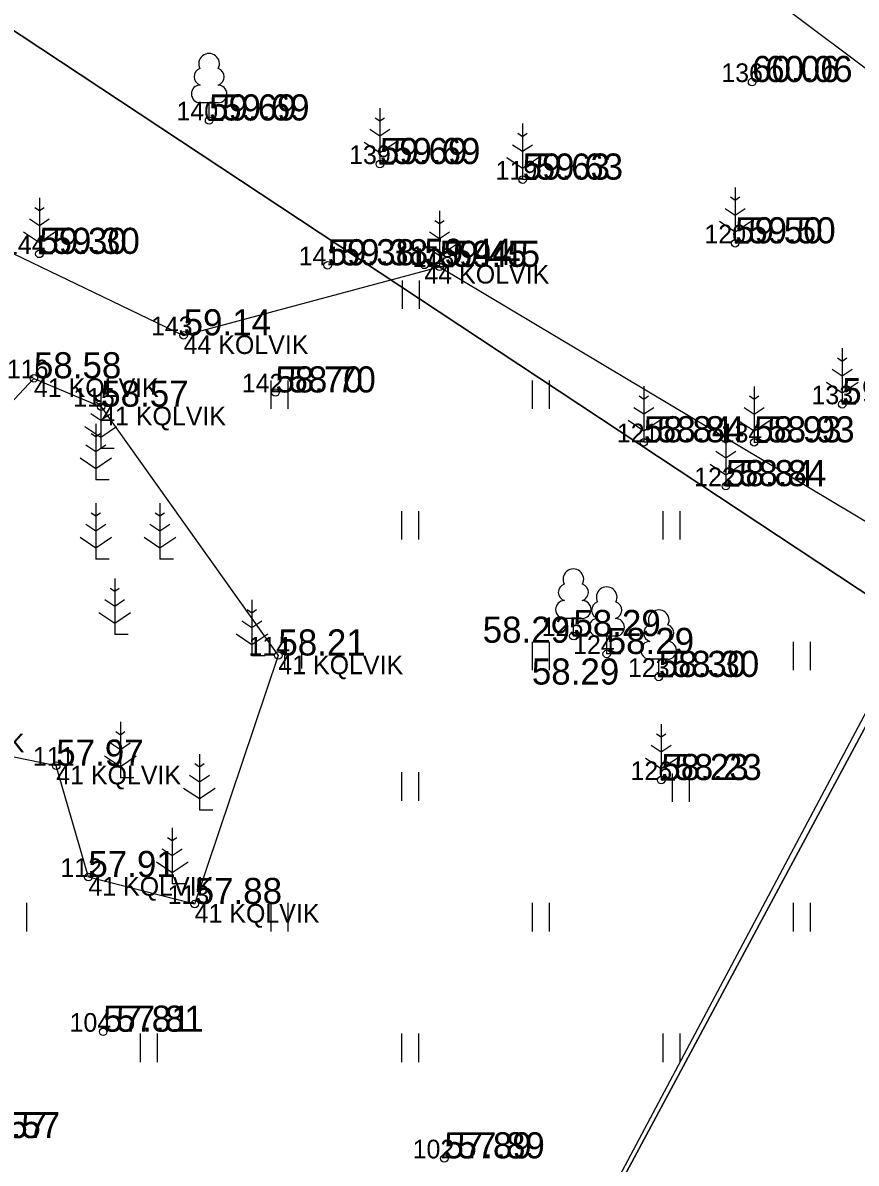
# Model space of a CAD drawing. Extents: x 640891 to 641083, y 6456526 to 6456669.
# Drawn here: x 640961.9 to 640984.23, y 6456618.41 to 6456648.96 of the extents above; entities that cross this region are included whole.
import ezdxf

# ---------------------------------------------------------------- set-up
doc = ezdxf.new("R2010")
doc.units = 0
for name, color, linetype in [('100koma2', 7, 'Continuous'), ('HALJASTUS', 7, 'Continuous'), ('KORGUS', 7, 'Continuous'), ('MOOTKORG', 7, 'Continuous'), ('MOOTMPUNKT', 7, 'Continuous'), ('MOOTNR', 7, 'Continuous'), ('MOOTPIIR', 7, 'Continuous'), ('PIIR', 7, 'Continuous'), ('PUU', 7, 'Continuous')]:
    doc.layers.add(name, color=color, linetype=linetype)

msp = doc.modelspace()

# ---------------------------------------------------------------- linework, layer by layer
at = {"layer": 'HALJASTUS'}
for p, q in [((640972.067, 6456642.056), (640972.067, 6456641.294)), ((640972.522, 6456642.056), (640972.522, 6456641.294)), ((640968.545, 6456639.381), (640968.545, 6456638.619)), ((640969, 6456639.381), (640969, 6456638.619)), ((640975.545, 6456639.381), (640975.545, 6456638.619)), ((640976, 6456639.381), (640976, 6456638.619)), ((640972.045, 6456635.881), (640972.045, 6456635.119)), ((640972.5, 6456635.881), (640972.5, 6456635.119)), ((640979.045, 6456635.881), (640979.045, 6456635.119)), ((640979.5, 6456635.881), (640979.5, 6456635.119)), ((640968.91, 6456632.425), (640968.91, 6456631.664)), ((640969.365, 6456632.425), (640969.365, 6456631.664)), ((640975.545, 6456632.381), (640975.545, 6456631.619)), ((640976, 6456632.381), (640976, 6456631.619)), ((640982.545, 6456632.381), (640982.545, 6456631.619)), ((640983, 6456632.381), (640983, 6456631.619)), ((640972.045, 6456628.881), (640972.045, 6456628.119)), ((640972.5, 6456628.881), (640972.5, 6456628.119)), ((640979.299, 6456628.852), (640979.299, 6456628.091)), ((640979.754, 6456628.852), (640979.754, 6456628.091)), ((640962, 6456625.381), (640962, 6456624.619)), ((640968.545, 6456625.381), (640968.545, 6456624.619)), ((640969, 6456625.381), (640969, 6456624.619)), ((640975.545, 6456625.381), (640975.545, 6456624.619)), ((640976, 6456625.381), (640976, 6456624.619)), ((640982.545, 6456625.381), (640982.545, 6456624.619)), ((640983, 6456625.381), (640983, 6456624.619)), ((640965.045, 6456621.881), (640965.045, 6456621.119)), ((640965.5, 6456621.881), (640965.5, 6456621.119)), ((640972.045, 6456621.881), (640972.045, 6456621.119)), ((640972.5, 6456621.881), (640972.5, 6456621.119)), ((640979.045, 6456621.881), (640979.045, 6456621.119)), ((640979.5, 6456621.881), (640979.5, 6456621.119))]:
    msp.add_line(p, q, dxfattribs=at)
for points in [[(640946.505, 6456648.924), (640957.822, 6456644.615), (640966.207, 6456640.588), (640973.066, 6456642.422), (640986.679, 6456634.293)], [(640940.859, 6456588.363), (640936.098, 6456589.959), (640937.267, 6456594.734), (640939.119, 6456600.434), (640944.153, 6456613.282), (640950.33, 6456623.315), (640954.177, 6456630.888), (640962.196, 6456639.436), (640963.998, 6456638.677), (640968.745, 6456632.01), (640966.503, 6456625.352), (640963.655, 6456626.075), (640962.794, 6456629.058), (640958.598, 6456629.914), (640954.818, 6456622.648), (640946.439, 6456612.875), (640948.12, 6456609.151), (640945.862, 6456604.895), (640949.763, 6456601.734), (640945.05, 6456592.964), (640940.483, 6456588.68)], [(640962.925, 6456576.62), (640957.383, 6456579.521), (640966.138, 6456596.056), (640972.417, 6456607.592), (640977.059, 6456616.501), (640985.041, 6456631.518)]]:
    msp.add_lwpolyline(points, dxfattribs=at)
at = {"layer": 'KORGUS'}
for centre in [(640981.44, 6456647.374), (640966.89, 6456646.344), (640971.467, 6456645.177), (640975.291, 6456644.76), (640980.987, 6456643.053), (640962.342, 6456642.77), (640970.066, 6456642.464), (640973.066, 6456642.422), (640968.666, 6456639.057), (640983.856, 6456638.741), (640978.539, 6456637.722), (640981.496, 6456637.721), (640980.738, 6456636.547), (640976.651, 6456632.531), (640977.544, 6456632.051), (640978.939, 6456631.436), (640979.007, 6456628.673), (640964.051, 6456621.93), (640973.194, 6456618.537)]:
    msp.add_circle(centre, 0.1, dxfattribs=at)
at = {"layer": 'MOOTMPUNKT'}
for centre in [(640981.44, 6456647.374), (640966.89, 6456646.344), (640971.467, 6456645.177), (640975.291, 6456644.76), (640980.987, 6456643.053), (640962.342, 6456642.77), (640970.066, 6456642.464), (640972.66, 6456642.475), (640973.066, 6456642.422), (640966.207, 6456640.588), (640962.196, 6456639.436), (640968.666, 6456639.057), (640963.998, 6456638.677), (640983.856, 6456638.741), (640978.539, 6456637.722), (640981.496, 6456637.721), (640980.738, 6456636.547), (640976.651, 6456632.531), (640968.745, 6456632.01), (640977.544, 6456632.051), (640978.939, 6456631.436), (640962.794, 6456629.058), (640979.007, 6456628.673), (640963.655, 6456626.075), (640966.503, 6456625.352), (640964.051, 6456621.93), (640973.194, 6456618.537)]:
    msp.add_circle(centre, 0.1, dxfattribs=at)
at = {"layer": 'MOOTPIIR'}
msp.add_lwpolyline([(640924.706, 6456598.502), (640938.233, 6456631.58), (640948.873, 6456653.866), (640953.873, 6456657.504), (640964.983, 6456662.356), (640986.497, 6456646.235), (640995.587, 6456643.81), (640989.565, 6456627.418), (640994.744, 6456619.938), (640993.953, 6456602.696)], dxfattribs=at)
at = {"layer": 'PIIR'}
msp.add_lwpolyline([(641039.59, 6456660.086), (641000.58, 6456623), (640985.89, 6456632.73), (640960.76, 6456649.34), (640935.64, 6456665.95), (640931.367, 6456668.776)], dxfattribs=at)
for points in [[(640957.22, 6456579.32), (640930.79, 6456593.51), (640960.76, 6456649.34), (640985.89, 6456632.73)], [(640983.63, 6456565.13), (640957.22, 6456579.32), (640985.89, 6456632.73), (641000.58, 6456623), (641011.01, 6456616.1)]]:
    msp.add_lwpolyline(points, close=True, dxfattribs=at)
at = {"layer": 'PUU'}
for p, q in [((640967.13, 6456646.819), (640966.65, 6456646.819)), ((640966.89, 6456646.344), (640966.89, 6456646.819)), ((640971.467, 6456646.677), (640971.467, 6456645.177)), ((640967.27, 6456646.344), (640966.89, 6456646.344)), ((640971.467, 6456646.327), (640971.342, 6456646.41)), ((640971.591, 6456646.41), (640971.467, 6456646.327)), ((640975.291, 6456646.26), (640975.291, 6456644.76)), ((640971.467, 6456645.927), (640971.2, 6456646.105)), ((640971.733, 6456646.105), (640971.467, 6456645.927)), ((640975.291, 6456645.91), (640975.167, 6456645.993)), ((640975.415, 6456645.993), (640975.291, 6456645.91)), ((640971.042, 6456645.766), (640971.467, 6456645.484)), ((640971.467, 6456645.484), (640971.891, 6456645.766)), ((640975.291, 6456645.51), (640975.024, 6456645.687)), ((640975.558, 6456645.687), (640975.291, 6456645.51)), ((640974.867, 6456645.349), (640975.291, 6456645.066)), ((640975.291, 6456645.066), (640975.715, 6456645.349)), ((640971.827, 6456645.177), (640971.467, 6456645.177)), ((640975.651, 6456644.76), (640975.291, 6456644.76)), ((640980.987, 6456644.203), (640980.863, 6456644.286)), ((640980.987, 6456644.553), (640980.987, 6456643.053)), ((640981.112, 6456644.286), (640980.987, 6456644.203)), ((640962.342, 6456643.92), (640962.217, 6456644.003)), ((640962.342, 6456644.27), (640962.342, 6456642.77)), ((640962.466, 6456644.003), (640962.342, 6456643.92)), ((640980.987, 6456643.803), (640980.721, 6456643.981)), ((640981.254, 6456643.981), (640980.987, 6456643.803)), ((640962.342, 6456643.52), (640962.075, 6456643.698)), ((640962.608, 6456643.698), (640962.342, 6456643.52)), ((640973.066, 6456643.922), (640973.066, 6456642.422)), ((640961.917, 6456643.36), (640962.342, 6456643.077)), ((640962.342, 6456643.077), (640962.766, 6456643.36)), ((640973.066, 6456643.572), (640972.942, 6456643.655)), ((640973.191, 6456643.655), (640973.066, 6456643.572)), ((640980.563, 6456643.643), (640980.987, 6456643.36)), ((640980.987, 6456643.36), (640981.412, 6456643.643)), ((640973.066, 6456643.172), (640972.8, 6456643.35)), ((640973.333, 6456643.35), (640973.066, 6456643.172)), ((640981.347, 6456643.053), (640980.987, 6456643.053)), ((640962.702, 6456642.77), (640962.342, 6456642.77)), ((640972.642, 6456643.012), (640973.066, 6456642.729)), ((640973.066, 6456642.729), (640973.491, 6456643.012)), ((640973.426, 6456642.422), (640973.066, 6456642.422)), ((640983.856, 6456640.241), (640983.856, 6456638.741)), ((640983.856, 6456639.891), (640983.732, 6456639.974)), ((640983.98, 6456639.974), (640983.856, 6456639.891)), ((640983.856, 6456639.491), (640983.589, 6456639.669)), ((640984.123, 6456639.669), (640983.856, 6456639.491)), ((640978.539, 6456639.222), (640978.539, 6456637.722)), ((640981.496, 6456639.221), (640981.496, 6456637.721)), ((640983.432, 6456639.331), (640983.856, 6456639.048)), ((640983.856, 6456639.048), (640984.28, 6456639.331)), ((640963.988, 6456638.703), (640963.864, 6456638.786)), ((640963.988, 6456639.053), (640963.988, 6456637.553)), ((640964.113, 6456638.786), (640963.988, 6456638.703)), ((640978.539, 6456638.872), (640978.415, 6456638.955)), ((640978.664, 6456638.955), (640978.539, 6456638.872)), ((640981.496, 6456638.871), (640981.371, 6456638.954)), ((640981.62, 6456638.954), (640981.496, 6456638.871)), ((640963.988, 6456638.303), (640963.722, 6456638.481)), ((640964.255, 6456638.481), (640963.988, 6456638.303)), ((640978.539, 6456638.472), (640978.273, 6456638.649)), ((640978.806, 6456638.649), (640978.539, 6456638.472)), ((640981.496, 6456638.471), (640981.229, 6456638.649)), ((640981.762, 6456638.649), (640981.496, 6456638.471)), ((640984.216, 6456638.741), (640983.856, 6456638.741)), ((640963.855, 6456638.215), (640963.855, 6456636.715)), ((640978.115, 6456638.311), (640978.539, 6456638.028)), ((640978.539, 6456638.028), (640978.964, 6456638.311)), ((640981.071, 6456638.31), (640981.496, 6456638.028)), ((640981.496, 6456638.028), (640981.92, 6456638.31)), ((640963.564, 6456638.143), (640963.988, 6456637.86)), ((640963.855, 6456637.865), (640963.731, 6456637.947)), ((640963.979, 6456637.947), (640963.855, 6456637.865)), ((640963.988, 6456637.86), (640964.413, 6456638.143)), ((640980.738, 6456638.047), (640980.738, 6456636.547)), ((640963.855, 6456637.465), (640963.588, 6456637.642)), ((640964.122, 6456637.642), (640963.855, 6456637.465)), ((640978.899, 6456637.722), (640978.539, 6456637.722)), ((640980.738, 6456637.697), (640980.614, 6456637.78)), ((640980.863, 6456637.78), (640980.738, 6456637.697)), ((640981.856, 6456637.721), (640981.496, 6456637.721)), ((640963.431, 6456637.304), (640963.855, 6456637.021)), ((640963.855, 6456637.021), (640964.279, 6456637.304)), ((640964.348, 6456637.553), (640963.988, 6456637.553)), ((640980.738, 6456637.297), (640980.472, 6456637.475)), ((640981.005, 6456637.475), (640980.738, 6456637.297)), ((640980.314, 6456637.137), (640980.738, 6456636.854)), ((640980.738, 6456636.854), (640981.163, 6456637.137)), ((640964.215, 6456636.715), (640963.855, 6456636.715)), ((640981.098, 6456636.547), (640980.738, 6456636.547)), ((640963.855, 6456636.092), (640963.855, 6456634.592)), ((640965.572, 6456636.092), (640965.572, 6456634.592)), ((640963.855, 6456635.742), (640963.731, 6456635.825)), ((640963.979, 6456635.825), (640963.855, 6456635.742)), ((640965.572, 6456635.742), (640965.448, 6456635.825)), ((640965.697, 6456635.825), (640965.572, 6456635.742)), ((640963.855, 6456635.342), (640963.588, 6456635.52)), ((640964.122, 6456635.52), (640963.855, 6456635.342)), ((640965.572, 6456635.342), (640965.305, 6456635.52)), ((640965.839, 6456635.52), (640965.572, 6456635.342)), ((640963.431, 6456635.181), (640963.855, 6456634.899)), ((640963.855, 6456634.899), (640964.279, 6456635.181)), ((640965.148, 6456635.181), (640965.572, 6456634.899)), ((640965.572, 6456634.899), (640965.996, 6456635.181)), ((640964.215, 6456634.592), (640963.855, 6456634.592)), ((640965.932, 6456634.592), (640965.572, 6456634.592)), ((640964.36, 6456634.071), (640964.36, 6456632.571)), ((640964.36, 6456633.721), (640964.236, 6456633.804)), ((640964.484, 6456633.804), (640964.36, 6456633.721)), ((640964.36, 6456633.321), (640964.093, 6456633.498)), ((640964.627, 6456633.498), (640964.36, 6456633.321)), ((640968.035, 6456633.499), (640968.035, 6456631.999)), ((640963.936, 6456633.16), (640964.36, 6456632.877)), ((640964.36, 6456632.877), (640964.784, 6456633.16)), ((640968.035, 6456633.149), (640967.911, 6456633.232)), ((640968.16, 6456633.232), (640968.035, 6456633.149)), ((640976.891, 6456633.006), (640976.411, 6456633.006)), ((640976.651, 6456632.531), (640976.651, 6456633.006)), ((640968.035, 6456632.749), (640967.769, 6456632.927)), ((640968.302, 6456632.927), (640968.035, 6456632.749)), ((640964.72, 6456632.571), (640964.36, 6456632.571)), ((640967.611, 6456632.589), (640968.035, 6456632.306)), ((640968.035, 6456632.306), (640968.46, 6456632.589)), ((640977.031, 6456632.531), (640976.651, 6456632.531)), ((640977.784, 6456632.526), (640977.304, 6456632.526)), ((640977.544, 6456632.051), (640977.544, 6456632.526)), ((640968.395, 6456631.999), (640968.035, 6456631.999)), ((640977.924, 6456632.051), (640977.544, 6456632.051)), ((640979.179, 6456631.911), (640978.699, 6456631.911)), ((640978.939, 6456631.436), (640978.939, 6456631.911)), ((640979.319, 6456631.436), (640978.939, 6456631.436)), ((640964.512, 6456630.23), (640964.512, 6456628.73)), ((640964.512, 6456629.88), (640964.387, 6456629.963)), ((640964.636, 6456629.963), (640964.512, 6456629.88)), ((640979.007, 6456630.173), (640979.007, 6456628.673)), ((640964.512, 6456629.48), (640964.245, 6456629.658)), ((640964.778, 6456629.658), (640964.512, 6456629.48)), ((640979.007, 6456629.823), (640978.882, 6456629.906)), ((640979.131, 6456629.906), (640979.007, 6456629.823)), ((640964.087, 6456629.319), (640964.512, 6456629.037)), ((640964.512, 6456629.037), (640964.936, 6456629.319)), ((640966.633, 6456629.371), (640966.633, 6456627.871)), ((640979.007, 6456629.423), (640978.74, 6456629.601)), ((640979.273, 6456629.601), (640979.007, 6456629.423)), ((640966.633, 6456629.021), (640966.508, 6456629.104)), ((640966.757, 6456629.104), (640966.633, 6456629.021)), ((640978.582, 6456629.262), (640979.007, 6456628.98)), ((640979.007, 6456628.98), (640979.431, 6456629.262)), ((640964.872, 6456628.73), (640964.512, 6456628.73)), ((640966.633, 6456628.621), (640966.366, 6456628.799)), ((640966.899, 6456628.799), (640966.633, 6456628.621)), ((640966.208, 6456628.46), (640966.633, 6456628.178)), ((640966.633, 6456628.178), (640967.057, 6456628.46)), ((640979.367, 6456628.673), (640979.007, 6456628.673)), ((640966.993, 6456627.871), (640966.633, 6456627.871)), ((640965.903, 6456627.394), (640965.903, 6456625.894)), ((640965.903, 6456627.044), (640965.778, 6456627.127)), ((640966.027, 6456627.127), (640965.903, 6456627.044)), ((640965.903, 6456626.644), (640965.636, 6456626.822)), ((640966.169, 6456626.822), (640965.903, 6456626.644)), ((640965.479, 6456626.484), (640965.903, 6456626.201)), ((640965.903, 6456626.201), (640966.327, 6456626.484)), ((640966.263, 6456625.894), (640965.903, 6456625.894))]:
    msp.add_line(p, q, dxfattribs=at)
for centre, radius, start, end in [((640966.89, 6456647.864), 0.277, 332.5799, 207.4201), ((640966.72, 6456647.516), 0.233, 109.0217, 253.1415), ((640967.061, 6456647.516), 0.233, 286.8508, 70.9859), ((640966.653, 6456647.056), 0.238, 90.0016, 269.3953), ((640967.128, 6456647.056), 0.238, 270.6047, 89.9984), ((640976.651, 6456634.051), 0.277, 332.5799, 207.4201), ((640976.481, 6456633.703), 0.233, 109.0217, 253.1415), ((640976.821, 6456633.703), 0.233, 286.8508, 70.9859), ((640977.544, 6456633.571), 0.277, 332.5799, 207.4201), ((640976.414, 6456633.243), 0.238, 90.0016, 269.3953), ((640976.889, 6456633.243), 0.238, 270.6047, 89.9984), ((640977.374, 6456633.224), 0.233, 109.0217, 253.1415), ((640977.714, 6456633.224), 0.233, 286.8508, 70.9859), ((640977.307, 6456632.764), 0.238, 90.0016, 269.3953), ((640977.781, 6456632.764), 0.238, 270.6047, 89.9984), ((640978.939, 6456632.956), 0.277, 332.5799, 207.4201), ((640978.769, 6456632.609), 0.233, 109.0217, 253.1415), ((640979.109, 6456632.609), 0.233, 286.8508, 70.9859), ((640978.701, 6456632.148), 0.238, 90.0016, 269.3953), ((640979.176, 6456632.148), 0.238, 270.6047, 89.9984)]:
    msp.add_arc(centre, radius, start, end, dxfattribs=at)

# ---------------------------------------------------------------- texts
at = {"layer": '100koma2'}
for s, p in [('44 KOLVIK', (640972.66, 6456641.975)), ('44 KOLVIK', (640966.207, 6456640.088)), ('41 KQLVIK', (640962.196, 6456638.936)), ('41 KQLVIK', (640963.998, 6456638.177)), ('41 KQLVIK', (640968.745, 6456631.51)), ('41 KQLVIK', (640958.598, 6456629.414)), ('41 KQLVIK', (640962.794, 6456628.558)), ('41 KQLVIK', (640963.655, 6456625.575)), ('41 KQLVIK', (640966.503, 6456624.852))]:
    msp.add_text(s, height=0.5, dxfattribs=at).set_placement(p)
at = {"layer": 'KORGUS'}
for s, p in [('60.06', (640981.79, 6456647.374)), ('59.69', (640967.24, 6456646.344)), ('59.69', (640971.817, 6456645.177)), ('59.63', (640975.641, 6456644.76)), ('59.50', (640981.337, 6456643.053)), ('59.30', (640962.692, 6456642.77)), ('59.38', (640970.416, 6456642.464)), ('59.45', (640973.416, 6456642.422)), ('58.70', (640969.016, 6456639.057)), ('58.84', (640978.889, 6456637.722)), ('58.93', (640981.846, 6456637.721)), ('58.84', (640981.088, 6456636.547)), ('58.29', (640974.221, 6456632.352)), ('58.30', (640979.289, 6456631.436)), ('58.29', (640975.538, 6456631.231)), ('58.23', (640979.357, 6456628.673)), ('57.81', (640964.401, 6456621.93)), ('57.57', (640960.557, 6456619.08)), ('57.89', (640973.544, 6456618.537))]:
    msp.add_text(s, height=0.7, dxfattribs=at).set_placement(p)
at = {"layer": 'MOOTKORG'}
for s, p in [('60.06', (640981.44, 6456647.374)), ('59.69', (640966.89, 6456646.344)), ('59.69', (640971.467, 6456645.177)), ('59.63', (640975.291, 6456644.76)), ('59.50', (640980.987, 6456643.053)), ('59.30', (640962.342, 6456642.77)), ('59.38', (640970.066, 6456642.464)), ('59.44', (640972.66, 6456642.475)), ('59.45', (640973.066, 6456642.422)), ('59.14', (640966.207, 6456640.588)), ('58.58', (640962.196, 6456639.436)), ('58.70', (640968.666, 6456639.057)), ('58.57', (640963.998, 6456638.677)), ('59.08', (640983.856, 6456638.741)), ('58.84', (640978.539, 6456637.722)), ('58.93', (640981.496, 6456637.721)), ('58.84', (640980.738, 6456636.547)), ('58.29', (640976.651, 6456632.531)), ('58.21', (640968.745, 6456632.01)), ('58.29', (640977.544, 6456632.051)), ('58.30', (640978.939, 6456631.436)), ('57.97', (640962.794, 6456629.058)), ('58.23', (640979.007, 6456628.673)), ('57.91', (640963.655, 6456626.075)), ('57.88', (640966.503, 6456625.352)), ('57.81', (640964.051, 6456621.93)), ('57.57', (640960.207, 6456619.08)), ('57.89', (640973.194, 6456618.537))]:
    msp.add_text(s, height=0.7, dxfattribs=at).set_placement(p)
at = {"layer": 'MOOTNR'}
for s, p in [('136', (640980.615, 6456647.374)), ('140', (640966.015, 6456646.344)), ('139', (640970.642, 6456645.177)), ('119', (640974.566, 6456644.76)), ('120', (640980.162, 6456643.053)), ('144', (640961.392, 6456642.77)), ('141', (640969.291, 6456642.464)), ('117', (640971.91, 6456642.475)), ('118', (640972.341, 6456642.422)), ('143', (640965.332, 6456640.588)), ('116', (640961.471, 6456639.436)), ('142', (640967.766, 6456639.057)), ('115', (640963.248, 6456638.677)), ('133', (640983.031, 6456638.741)), ('121', (640977.815, 6456637.722)), ('134', (640980.596, 6456637.721)), ('122', (640979.888, 6456636.547)), ('125', (640975.801, 6456632.531)), ('114', (640967.945, 6456632.01)), ('124', (640976.644, 6456632.051)), ('123', (640978.114, 6456631.436)), ('111', (640962.169, 6456629.058)), ('126', (640978.182, 6456628.673)), ('112', (640962.905, 6456626.075)), ('113', (640965.778, 6456625.352)), ('104', (640963.151, 6456621.93)), ('102', (640972.344, 6456618.537))]:
    msp.add_text(s, height=0.5, dxfattribs=at).set_placement(p)

doc.saveas('drawing.dxf')
